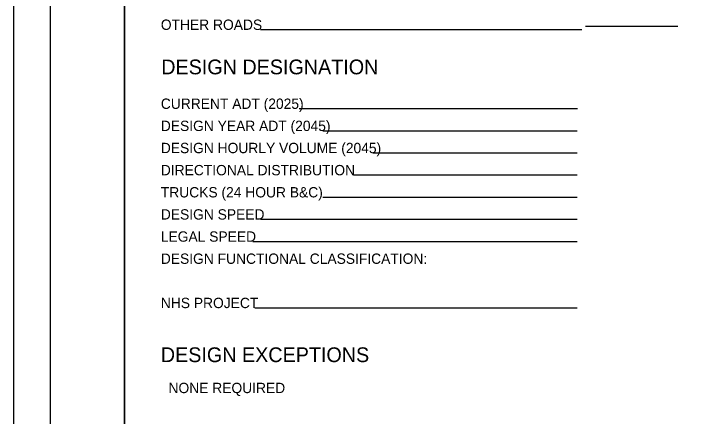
# Model space of a CAD drawing. Extents: x -7.3 to 34, y 0 to 22.
# Drawn here: x 0 to 9.25, y 5.64 to 11.1 of the extents above; entities that cross this region are included whole.
import ezdxf

# ---------------------------------------------------------------- set-up
doc = ezdxf.new("R2010")
doc.units = 0
for name, color, linetype in [('SH_Border', 7, 'Continuous'), ('SH_Cut_Line', 7, 'Continuous'), ('SH_Data', 7, 'Continuous'), ('SH_Text', 7, 'Continuous')]:
    doc.layers.add(name, color=color, linetype=linetype)

msp = doc.modelspace()

# ---------------------------------------------------------------- linework, layer by layer
at = {"layer": 'SH_Border'}
for points in [[(0.5, 21.5), (1.5, 21.5), (1.5, 0.5), (0.5, 0.5)], [(1.5, 21.5), (33.5, 21.5), (33.5, 0.5), (1.5, 0.5)]]:
    msp.add_lwpolyline(points, close=True, dxfattribs=at)
at = {"layer": 'SH_Cut_Line'}
msp.add_lwpolyline([(0, 0), (34, 0), (34, 22), (0, 22)], close=True, dxfattribs=at)
at = {"layer": 'SH_Data'}
for p, q in [((9, 10.9223), (7.75, 10.9223)), ((7.7, 10.8767), (3.3471, 10.8767)), ((7.6424, 9.8062), (3.871, 9.8062)), ((7.6368, 9.5062), (4.1885, 9.5062)), ((7.6368, 9.2062), (4.8723, 9.2062)), ((7.6368, 8.9062), (4.6037, 8.9062)), ((7.6368, 8.6062), (4.1885, 8.6062)), ((7.6368, 8.3062), (3.346, 8.3062)), ((7.6368, 8.0062), (3.2422, 8.0062)), ((7.6368, 7.1062), (3.2669, 7.1062))]:
    msp.add_line(p, q, dxfattribs=at)

# ---------------------------------------------------------------- texts
msp.add_text('DESIGN DESIGNATION', height=0.2, dxfattribs=at).set_placement((2, 10.2747))
at = {"layer": 'SH_Text'}
for s, height, p in [('OTHER ROADS', 0.14, (1.9944, 10.8767)), ('CURRENT ADT (2025)', 0.14, (1.9944, 9.8062)), ('DESIGN YEAR ADT (2045)', 0.14, (1.9944, 9.5062)), ('DESIGN HOURLY VOLUME (2045)', 0.14, (1.9944, 9.2062)), ('DIRECTIONAL DISTRIBUTION', 0.14, (1.9944, 8.9062)), ('TRUCKS (24 HOUR B&C)', 0.14, (1.9944, 8.6062)), ('DESIGN SPEED', 0.14, (1.9944, 8.3062)), ('LEGAL SPEED', 0.14, (1.9944, 8.0062)), ('DESIGN FUNCTIONAL CLASSIFICATION:', 0.14, (1.9944, 7.7062)), ('NHS PROJECT', 0.14, (1.9944, 7.1062)), ('DESIGN EXCEPTIONS', 0.2, (1.9944, 6.3744)), ('  NONE REQUIRED                          ', 0.14, (1.9944, 5.9544))]:
    msp.add_text(s, height=height, dxfattribs=at).set_placement(p)

doc.saveas('drawing.dxf')
